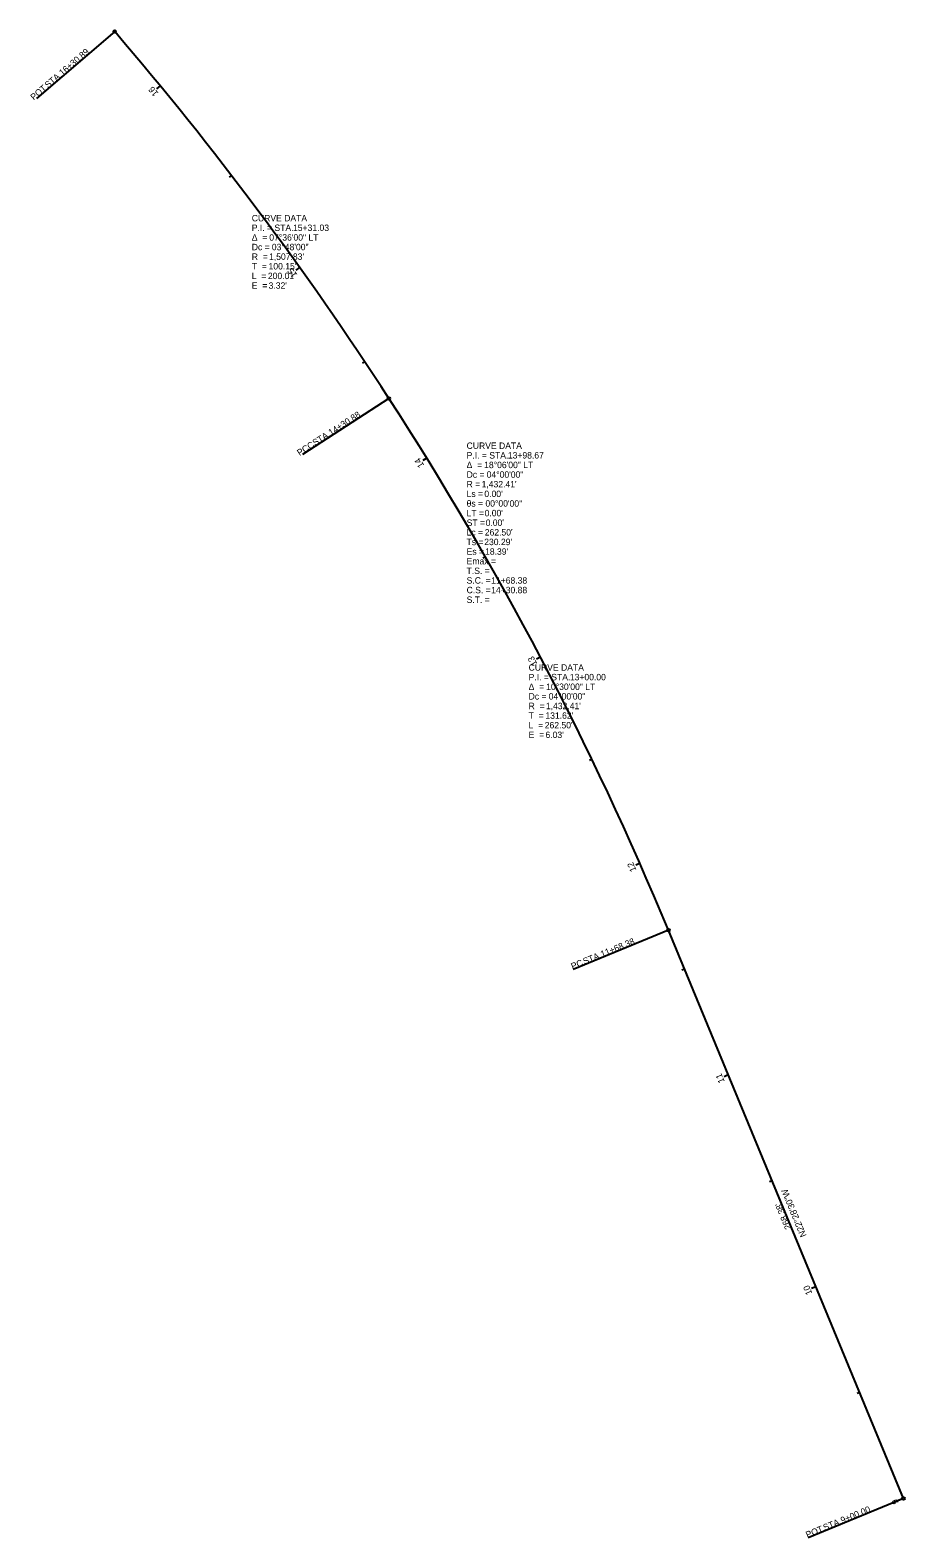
# Model space of a CAD drawing. Extents: x 2043343 to 2043725, y 635132 to 635790.
import ezdxf

# ---------------------------------------------------------------- set-up
doc = ezdxf.new("R2010")
doc.units = 0
for name, color, linetype in [('RW_X_CL', 7, 'Continuous'), ('RW_X_CL_100_Bearings', 7, 'Continuous'), ('RW_X_CL_100_Cardinal_Points', 7, 'Continuous'), ('RW_X_CL_100_Curve_Data', 7, 'Continuous'), ('RW_X_CL_100_Distances', 7, 'Continuous'), ('RW_X_CL_100_Stations', 7, 'Continuous')]:
    doc.layers.add(name, color=color, linetype=linetype)

msp = doc.modelspace()

# ---------------------------------------------------------------- linework, layer by layer
at = {"layer": 'RW_X_CL'}
msp.add_line((2043724.27, 635148.91), (2043621.68, 635396.9), dxfattribs=at)
for centre, radius, start, end in [((2042234.79, 634808.27), 1507.83, 32.97514, 40.57514), ((2042298.06, 634849.32), 1432.41, 22.47514, 32.97514)]:
    msp.add_arc(centre, radius, start, end, dxfattribs=at)
at = {"layer": 'RW_X_CL_100_Cardinal_Points'}
for p, q in [((2043380.07, 635789.03), (2043345.89, 635759.76)), ((2043499.72, 635628.94), (2043461.97, 635604.45)), ((2043621.68, 635396.9), (2043580.09, 635379.7)), ((2043724.27, 635148.91), (2043682.69, 635131.71))]:
    msp.add_line(p, q, dxfattribs=at)
for centre in [(2043380.07, 635789.03), (2043499.72, 635628.94), (2043621.68, 635396.9), (2043724.27, 635148.91)]:
    msp.add_circle(centre, 0.6, dxfattribs=at)
at = {"layer": 'RW_X_CL_100_Stations'}
for p, q in [((2043399.92, 635765.36), (2043398.38, 635764.09)), ((2043431.01, 635726.21), (2043430.06, 635725.48)), ((2043460.79, 635686.05), (2043459.16, 635684.88)), ((2043489.22, 635644.92), (2043488.22, 635644.25)), ((2043516.25, 635602.86), (2043514.55, 635601.81)), ((2043541.81, 635559.88), (2043540.77, 635559.29)), ((2043565.85, 635516.05), (2043564.08, 635515.12)), ((2043588.34, 635471.4), (2043587.26, 635470.87)), ((2043609.27, 635425.99), (2043607.44, 635425.18)), ((2043628.7, 635379.92), (2043627.59, 635379.46)), ((2043647.82, 635333.72), (2043645.97, 635332.95)), ((2043666.93, 635287.52), (2043665.82, 635287.06)), ((2043686.05, 635241.31), (2043684.2, 635240.55)), ((2043705.16, 635195.11), (2043704.05, 635194.65)), ((2043724.27, 635148.91), (2043722.43, 635148.14))]:
    msp.add_line(p, q, dxfattribs=at)

# ---------------------------------------------------------------- texts
at = {"layer": 'RW_X_CL_100_Bearings'}
msp.add_text('N22°28\'30"W', height=2.8, rotation=112.47514, dxfattribs=at).set_placement((2043682.01, 635263.63))
at = {"layer": 'RW_X_CL_100_Cardinal_Points'}
for s, rotation, p in [('16+30.89', 40.57514, (2043357.27, 635769.55)), ('POT', 40.57514, (2043344.77, 635758.85)), (' STA. ', 40.57514, (2043350.19, 635763.49)), ('14+30.88', 32.97514, (2043474.45, 635612.59)), (' STA. ', 32.97514, (2043466.63, 635607.52)), ('PCC', 32.97514, (2043460.79, 635603.73)), ('11+68.38', 22.47514, (2043592.76, 635384.98)), ('PC', 22.47514, (2043579.89, 635379.66)), (' STA. ', 22.47514, (2043584.15, 635381.42)), ('9+00.00', 22.47514, (2043697.54, 635137.89)), ('POT', 22.47514, (2043682.34, 635131.6)), (' STA. ', 22.47514, (2043688.93, 635134.33))]:
    msp.add_text(s, height=2.8, rotation=rotation, dxfattribs=at).set_placement(p)
at = {"layer": 'RW_X_CL_100_Curve_Data'}
for s, p in [('CURVE DATA', (2043439.9, 635706.19)), ('Δ  = ', (2043439.9, 635697.79)), ('P.I. = STA. ', (2043439.9, 635701.99)), ('07°36\'00" LT', (2043447.54, 635697.79)), ('15+31.03', (2043457.89, 635701.99)), ('Dc = ', (2043439.9, 635693.59)), ('03°48\'00"', (2043448.64, 635693.59)), ('T  = ', (2043439.9, 635685.19)), ('R  = ', (2043439.9, 635689.39)), ("100.15'", (2043447.22, 635685.19)), ("1,507.83'", (2043447.43, 635689.39)), ('L  = ', (2043439.9, 635680.99)), ('E  = ', (2043439.9, 635676.79)), ("200.01'", (2043446.93, 635680.99)), ("3.32'", (2043447.24, 635676.79)), ('CURVE DATA', (2043533.64, 635606.9)), ('Δ  = ', (2043533.64, 635598.5)), ('P.I. = STA. ', (2043533.64, 635602.7)), ('18°06\'00" LT', (2043541.29, 635598.5)), ('13+98.67', (2043551.63, 635602.7)), ('Dc = ', (2043533.64, 635594.3)), ('04°00\'00"', (2043542.39, 635594.3)), ('R = ', (2043533.64, 635590.1)), ('Ls = ', (2043533.64, 635585.9)), ("1,432.41'", (2043540.18, 635590.1)), ("0.00'", (2043541.39, 635585.9)), ('θs = ', (2043533.64, 635581.7)), ('00°00\'00"', (2043541.85, 635581.7)), ('ST = ', (2043533.64, 635573.3)), ('LT = ', (2043533.64, 635577.5)), ("0.00'", (2043541.49, 635577.5)), ("0.00'", (2043541.94, 635573.3)), ('Ts = ', (2043533.64, 635564.9)), ('Lc = ', (2043533.64, 635569.1)), ("230.29'", (2043541.33, 635564.9)), ("262.50'", (2043541.56, 635569.1)), ('Es = ', (2043533.64, 635560.7)), ("18.39'", (2043541.7, 635560.7)), ('T.S. = ', (2043533.64, 635552.3)), ('Emax = ', (2043533.64, 635556.5)), ('S.C. = ', (2043533.64, 635548.1)), ('11+68.38', (2043544.35, 635548.1)), ('S.T. = ', (2043533.64, 635539.7)), ('C.S. = ', (2043533.64, 635543.9)), ('14+30.88', (2043544.35, 635543.9)), ('CURVE DATA', (2043560.7, 635510.12)), ('P.I. = STA. ', (2043560.7, 635505.92)), ('13+00.00', (2043578.69, 635505.92)), ('Δ  = ', (2043560.7, 635501.72)), ('10°30\'00" LT', (2043568.35, 635501.72)), ('Dc = ', (2043560.7, 635497.52)), ('R  = ', (2043560.7, 635493.32)), ("1,432.41'", (2043568.23, 635493.32)), ('04°00\'00"', (2043569.44, 635497.52)), ('T  = ', (2043560.7, 635489.12)), ("131.62'", (2043568.02, 635489.12)), ('L  = ', (2043560.7, 635484.92)), ('E  = ', (2043560.7, 635480.72)), ("262.50'", (2043567.74, 635484.92)), ("6.03'", (2043568.04, 635480.72))]:
    msp.add_text(s, height=2.8, dxfattribs=at).set_placement(p)
at = {"layer": 'RW_X_CL_100_Distances'}
msp.add_text("268.38'", height=2.8, rotation=112.47514, dxfattribs=at).set_placement((2043675.4, 635266.94))
at = {"layer": 'RW_X_CL_100_Stations'}
for s, rotation, p in [('16', 129.40139, (2043399.35, 635762.13)), ('15', 125.60151, (2043459.97, 635682.89)), ('14', 121.73983, (2043515.26, 635599.7)), ('13', 117.73988, (2043564.6, 635513.04)), ('12', 113.73992, (2043607.82, 635423.06)), ('11', 112.47514, (2043646.31, 635330.82)), ('10', 112.47514, (2043684.56, 635238.37)), ('9', 112.47514, (2043722.34, 635147.04))]:
    msp.add_text(s, height=2.8, rotation=rotation, dxfattribs=at).set_placement(p)

doc.saveas('drawing.dxf')
